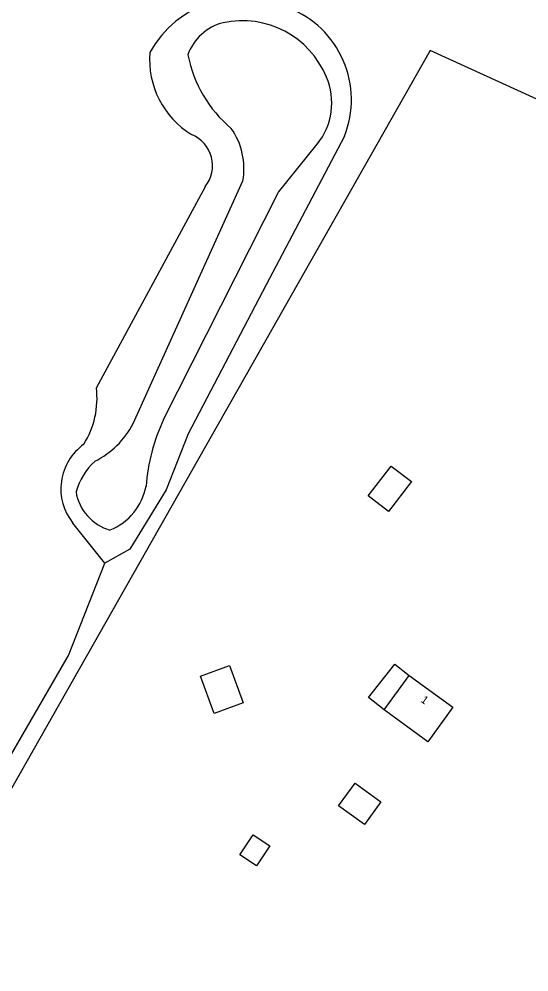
# Model space of a CAD drawing. Extents: x 124000 to 129000, y 395500 to 397503.
# Drawn here: x 127835.6 to 127899.3, y 396131.9 to 396251 of the extents above; entities that cross this region are included whole.
import ezdxf

# ---------------------------------------------------------------- set-up
doc = ezdxf.new("R2010")
doc.units = 0
for name, color, linetype in [('gg-anno-huisnummerreeks BGT', 7, 'Continuous'), ('gg-bbg-bijgebouw', 7, 'Continuous'), ('gg-bbg-gedigitaliseerde bijgebouw', 7, 'Continuous'), ('gg-bbg-hoofdgebouw', 7, 'Continuous'), ('gg-bbg-luifel en loopbrug', 7, 'Continuous'), ('gg-kntw-bovenkant insteek waterloop', 7, 'Continuous'), ('gg-kntw-waterlijn', 7, 'Continuous'), ('gt-grn-groengrens', 7, 'Continuous'), ('gt-grn-vlakafsluiter', 7, 'Continuous')]:
    doc.layers.add(name, color=color, linetype=linetype)

msp = doc.modelspace()

# ---------------------------------------------------------------- linework, layer by layer
at = {"layer": 'gg-bbg-bijgebouw'}
msp.add_lwpolyline([(127881.74, 396189.44), (127879.2, 396191.4), (127882.07, 396195.11), (127884.6, 396193.16), (127881.74, 396189.44)], dxfattribs=at)
at = {"layer": 'gg-bbg-gedigitaliseerde bijgebouw'}
for points in [[(127877.55, 396155.47), (127880.79, 396153.12), (127878.74, 396150.29), (127875.5, 396152.64), (127877.55, 396155.47)], [(127864.81, 396149), (127866.89, 396147.63), (127865.24, 396145.12), (127863.15, 396146.5), (127864.81, 396149)]]:
    msp.add_lwpolyline(points, dxfattribs=at)
at = {"layer": 'gg-bbg-hoofdgebouw'}
msp.add_line((127881.21, 396164.62), (127884.33, 396168.94), dxfattribs=at)
msp.add_lwpolyline([(127884.33, 396168.94), (127889.8, 396164.96), (127886.67, 396160.65), (127881.21, 396164.62)], dxfattribs=at)
at = {"layer": 'gg-bbg-luifel en loopbrug'}
for points in [[(127858.25, 396168.83), (127861.87, 396170.19), (127863.58, 396165.51), (127859.95, 396164.18), (127858.25, 396168.83)], [(127881.21, 396164.62), (127879.25, 396166.18), (127882.54, 396170.35), (127884.33, 396168.94)]]:
    msp.add_lwpolyline(points, dxfattribs=at)
at = {"layer": 'gg-kntw-bovenkant insteek waterloop'}
for p, q in [((127845.22, 396204.87), (127858.84, 396230.05)), ((127846.28, 396182.98), (127842.29, 396187.98))]:
    msp.add_line(p, q, dxfattribs=at)
for points in [[(127876.22, 396236.34), (127866.45, 396217.74), (127856.68, 396199.13)], [(127856.68, 396199.13), (127853.93, 396192.12), (127849.4, 396184.7), (127846.28, 396182.98)]]:
    msp.add_lwpolyline(points, dxfattribs=at)
for centre, radius, start, end in [((127863.52, 396240.43), 13.25, 64.1936, 151.3533), ((127864.78, 396240.9), 12.32, 338.285, 68.52), ((127862.91, 396245.96), 11.05, 175.7247, 238.4392), ((127855.55, 396232.65), 4.19, 321.6313, 67.9653), ((127834.6, 396203.56), 10.7, 327.6454, 7.0628), ((127847.61, 396192.27), 6.83, 125.5045, 218.8676)]:
    msp.add_arc(centre, radius, start, end, dxfattribs=at)
at = {"layer": 'gg-kntw-waterlijn'}
for p, q in [((127867.98, 396229.33), (127872.83, 396235.35)), ((127849.81, 396200.42), (127863.53, 396230.74)), ((127853.62, 396200.92), (127867.98, 396229.33))]:
    msp.add_line(p, q, dxfattribs=at)
for centre, radius, start, end in [((127862.64, 396244.36), 6.36, 104.2711, 160.3021), ((127863.45, 396239.37), 11.4, 22.4819, 102.0189), ((127872.34, 396249.56), 15.98, 191.0236, 229.98), ((127866.52, 396240.48), 8.13, 320.8638, 23.5314), ((127855.05, 396232.3), 8.62, 349.5183, 35.5614), ((127874.65, 396190.93), 23.28, 154.6135, 175.8776), ((127840.3, 396205.29), 10.68, 296.1834, 332.9016), ((127850.75, 396189.55), 8.4, 132.9944, 163.8242), ((127844.21, 396193.94), 7.34, 291.6805, 349.5671), ((127848.52, 396192.81), 5.92, 188.915, 254.2716)]:
    msp.add_arc(centre, radius, start, end, dxfattribs=at)
at = {"layer": 'gt-grn-groengrens'}
msp.add_lwpolyline([(127793.75, 396083.3), (127792.95, 396087.48), (127804.45, 396110.38), (127821.76, 396136.98), (127841.75, 396171.41), (127846.28, 396182.98)], dxfattribs=at)
at = {"layer": 'gt-grn-vlakafsluiter'}
msp.add_lwpolyline([(127972.71, 396207.92), (127886.95, 396247.06), (127832.31, 396150.83), (127793.75, 396083.3)], dxfattribs=at)

# ---------------------------------------------------------------- texts
at = {"layer": 'gg-anno-huisnummerreeks BGT'}
msp.add_text('1', height=1, rotation=324, dxfattribs=at).set_placement((127885.68, 396165.7))

doc.saveas('drawing.dxf')
